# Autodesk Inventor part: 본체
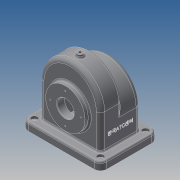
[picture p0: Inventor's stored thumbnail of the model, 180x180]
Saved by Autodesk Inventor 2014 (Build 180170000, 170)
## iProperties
Created: 2017-11
Part Number: 본체
Material: Generic
Document SubType Name: Modeling
Designer: sda
Density: 1 g/cm^3
Appearance: Default
Author: sda
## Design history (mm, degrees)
sketch "스케치1"
  geometry: L1 (-58, 0)-(58, 0); L2 (-58, 0)-(-58, 65); L3 (58, 0)-(58, 65); A1 r 58 centre (0, 65) between (58, 65) and (-58, 65); 2 further points
  constraints: 6 end point, 2 point on circle, 2 tangent, 1 centre point, 1 coincident, 1 horizontal, 1 midpoint, 1 parallel, 1 perpendicular
  dimensions: "d7" = 116 distance between parallel lines of L2 L3; "d8" = 65 distance from line of L1 L2.end
extrude "돌출1" new body sketch "스케치1" distance "d2" = 38; taper "d3" = 0 deg
sketch "스케치2"
  geometry: L1 (-58, 0)-(58, 0) reference; L2 (58, 0)-(58, 65) reference; L3 (-58, 65)-(-58, 0) reference; L4 (-58, 0)-(58, 0); L5 (58, 0)-(58, 42); L6 (-58, 0)-(-58, 42); A1 r 58 centre (0, 42) between (58, 42) and (-58, 42); 1 further point
  constraints: 6 end point, 2 point on circle, 2 point on line, 2 tangent, 1 centre point, 1 collinear, 1 perpendicular
  dimensions: "d5" = 58 radius of A1 (derived); "d9" = 42 distance from line of L6.end L1
extrude "돌출2" join sketch "스케치2" distance "d10" = 38; taper "d11" = 0 deg
node "작업 평면1"
feature "쉘1" dims "d128" = 5
sketch "스케치19"
  geometry: L1 (111, -71)-(5, -71) reference; L2 (5, -71)-(5, -5) reference; L3 (5, -5)-(111, -5) reference; L4 (111, -5)-(111, -71) reference; L5 (0, 0)-(116, 0) reference; L6 (0, 0)-(0, -76) reference; L7 (-5, 17)-(121, 17); L8 (133, 5)-(133, -81); L9 (121, -93)-(-5, -93); L10 (-17, -81)-(-17, 5); A1 r 12 centre (-5, 5) between (-5, 17) and (-17, 5); A2 r 12 centre (-5, -81) between (-17, -81) and (-5, -93); A3 r 12 centre (121, -81) between (121, -93) and (133, -81); A4 r 12 centre (121, 5) between (133, 5) and (121, 17); 5 further points
  constraints: 8 end point, 8 point on circle, 8 tangent, 4 centre point, 4 midpoint, 3 equal radius, 2 parallel, 1 horizontal, 1 horizontal alignment, 1 perpendicular, 1 vertical alignment
  dimensions: "d129" = 150 distance between parallel lines of L8 L10; "d130" = 110 distance between parallel lines of L9 L7; "d131" = 12 radius of A1
extrude "돌출13" join sketch "스케치19" distance "d132" = 15; taper "d133" = 0 deg
node "작업 평면2"
sketch "스케치20"
  geometry: C1 r 6 at (0, -19); 1 further point
  constraints: 1 centre point, 1 vertical alignment
  dimensions: "d135" = 12 diameter of C1; "d136" = 19 distance of point (0, 0) C1.centre
extrude "돌출14" join sketch "스케치20" stored distance "d137" = 15; taper "d138" = 0 deg
hole "구멍7" diameter "d141" = 4.459; stored, may be unused: countersink angle "d145" = 90 deg, drill point angle "d147" = 0 deg; dims "d142" = 100, "d143" = 4, "d144" = 2, "d146" = 8, "d148" = 10, "d149" = 10
sketch "스케치21"
  geometry: L1 (63, -15)-(-63, -15) reference; C1 r 37.5 at (0, 50); 2 further points
  constraints: 1 centre point, 1 midpoint, 1 vertical alignment
  dimensions: "d150" = 75 diameter of C1; "d151" = 65 distance from line of L1 C1.centre
extrude "돌출15" join sketch "스케치21" distance "d152" = 9; taper "d153" = 0 deg
sketch "스케치22"
  geometry: L1 (63, -15)-(-63, -15) reference; C1 r 31 at (0, 50); 2 further points
  constraints: 1 centre point, 1 midpoint, 1 vertical alignment
  dimensions: "d154" = 62 diameter of C1; "d155" = 65 distance from line of L1 C1.centre
extrude "돌출16" join sketch "스케치22" distance "d156" = 10; taper "d157" = 0 deg
sketch "스케치23"
  geometry: C1 r 37.5 at (0, 0) reference; C2 r 16 at (0, 0); 1 further point
  constraints: 1 centre point, 1 coincident
  dimensions: "d158" = 32 diameter of C2
extrude "돌출17" cut sketch "스케치23" stored distance "d159" = 10; taper "d160" = 0 deg
sketch "스케치24"
  geometry: C1 r 16 at (0, 0) reference; 2 further points
  constraints: 1 vertical alignment
  dimensions: "d161" = 29 distance of C1.centre point (0, 29)
hole "구멍8" sketch "스케치24" at (0, 29) diameter "d162" = 2.459; stored, may be unused: countersink angle "d166" = 90 deg, drill point angle "d168" = 118 deg; dims "d163" = 6, "d164" = 4, "d165" = 2, "d167" = 8
sketch "스케치25" dims "d172" = 52
  geometry: C1 r 16 at (0, 0) reference; C2 r 31 at (0, 0) reference; 3 further points
  constraints: 2 vertical alignment, 1 coincident, 2 other
  dimensions: "d173" = 26 distance of C1.centre point (0, 26) (derived)
hole "구멍9" sketch "스케치25" at (0, 26) diameter "d174" = 2.459; stored, may be unused: countersink angle "d178" = 90 deg, drill point angle "d180" = 118 deg; dims "d175" = 6, "d176" = 4, "d177" = 2, "d179" = 8
sketch "스케치26"
  geometry: C1 r 6 at (-5, 81); C2 r 6 at (121, 81); C3 r 6 at (121, -5); C4 r 6 at (-5, -5); C5 r 2.5 at (-5, 81); C6 r 2.5 at (121, 81); C7 r 2.5 at (121, -5); C8 r 2.5 at (-5, -5); A1 r 12 centre (-5, -5) between (-17, -5) and (-5, -17) reference; A2 r 12 centre (121, -5) between (121, -17) and (133, -5) reference; A3 r 12 centre (121, 81) between (133, 81) and (121, 93) reference; A4 r 12 centre (-5, 81) between (-5, 93) and (-17, 81) reference; 1 further point
  constraints: 8 centre point, 8 coincident
  dimensions: "d184" = 12 diameter of C1; "d186" = 12 diameter of C2; "d188" = 12 diameter of C3; "d189" = 12 diameter of C4; "d190" = 5 diameter of C5; "d191" = 5 diameter of C6; "d192" = 5 diameter of C7; "d193" = 5 diameter of C8
extrude "돌출18" cut sketch "스케치26" stored distance "d194" = 10; taper "d195" = 0 deg
extrude "돌출19" cut sketch "스케치26" distance "d196" = 5; taper "d197" = 0 deg
fillet "모깎기2" dims "d198" = 8, "d199" = 3
chamfer "모따기1" distance "d200" = 1; stored, may be unused: second distance "d201" = 2, angle "d202" = 45 deg
sketch "스케치27"
  geometry: L1 (-8, 62)-(-8, 0) reference; L2 (73, -18)-(-13, -18) reference; 2 further points
  constraints: 1 other
  dimensions: "d203" = 38 distance from line of point (30, 22) L1; "d204" = 40 distance from line of L2 point (30, 22)
extrude "돌출20" join sketch "스케치27" distance "d205" = 0.5; taper "d206" = 0 deg
node "솔리드1"
pattern_circular "원형 패턴5" dims angle "d170" = 360 deg
pattern_circular "원형 패턴6" dims angle "d182" = 360 deg
other parameters: "d35" = 129, "d134" = 129
